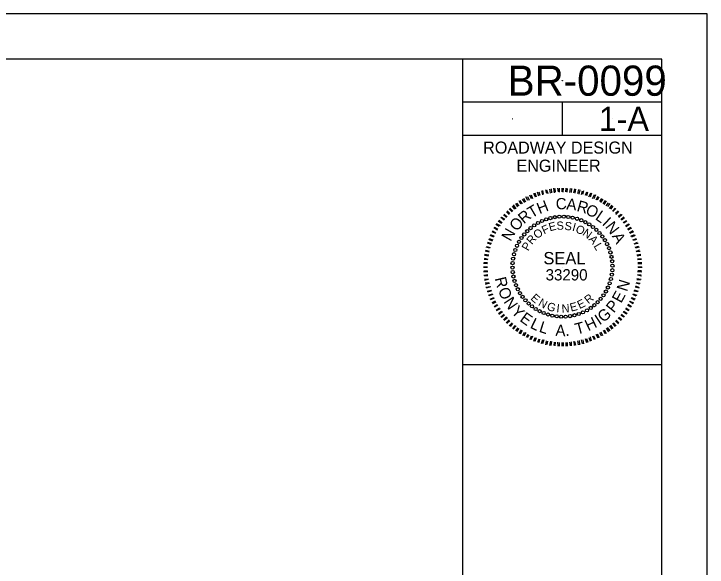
# Model space of a CAD drawing. Extents: x 1844369 to 1844800, y 671424 to 671721.
# Drawn here: x 1844552.92 to 1844581.79, y 671570.09 to 671593.11 of the extents above; entities that cross this region are included whole.
import ezdxf

# ---------------------------------------------------------------- set-up
doc = ezdxf.new("R2010")
doc.units = 0
for name, color, linetype in [('P_NCDOT_Roadway_Bridge', 7, 'Continuous'), ('Prop DSN Text', 7, 'Continuous'), ('Sheet PE Seal Cell', 7, 'Continuous'), ('Sheet Plan CELL', 7, 'Continuous'), ('Sheet_Clip_Boundary_CELL', 7, 'Continuous'), ('Sheet_Plan_CELL', 7, 'Continuous'), ('Sheet_Title_Block_Text', 7, 'Continuous')]:
    doc.layers.add(name, color=color, linetype=linetype)

msp = doc.modelspace()

# ---------------------------------------------------------------- linework, layer by layer
at = {"layer": 'P_NCDOT_Roadway_Bridge'}
for centre in [(1844575.761, 671590.327), (1844575.761, 671590.327), (1844573.689, 671588.741), (1844573.689, 671588.741), (1844577.833, 671588.741), (1844577.833, 671588.741), (1844571.617, 671588.051)]:
    msp.add_ellipse(centre, major_axis=(0, 0.00502), ratio=0.990582, dxfattribs=at)
at = {"layer": 'Sheet PE Seal Cell'}
for p, q in [((1844574.944, 671585.581), (1844574.902, 671585.739)), ((1844574.935, 671585.752), (1844574.966, 671585.599)), ((1844575.107, 671585.636), (1844575.076, 671585.788)), ((1844575.104, 671585.79), (1844575.147, 671585.632)), ((1844575.266, 671585.65), (1844575.24, 671585.814)), ((1844575.29, 671585.834), (1844575.3, 671585.663)), ((1844575.425, 671585.664), (1844575.409, 671585.852)), ((1844575.444, 671585.837), (1844575.464, 671585.689)), ((1844575.594, 671585.702), (1844575.575, 671585.849)), ((1844575.62, 671585.858), (1844575.629, 671585.687)), ((1844575.748, 671585.705), (1844575.746, 671585.859)), ((1844575.786, 671585.855), (1844575.783, 671585.689)), ((1844575.902, 671585.707), (1844575.923, 671585.851)), ((1844575.963, 671585.848), (1844575.949, 671585.687)), ((1844576.07, 671585.676), (1844576.101, 671585.844)), ((1844576.141, 671585.84), (1844576.127, 671585.68)), ((1844576.242, 671585.657), (1844576.273, 671585.824)), ((1844576.308, 671585.809), (1844576.282, 671585.654)), ((1844576.398, 671585.631), (1844576.445, 671585.805)), ((1844576.48, 671585.79), (1844576.444, 671585.611)), ((1844576.56, 671585.589), (1844576.602, 671585.751)), ((1844576.642, 671585.747), (1844576.6, 671585.585)), ((1844574.324, 671585.336), (1844574.241, 671585.497)), ((1844574.303, 671585.512), (1844574.374, 671585.356)), ((1844574.48, 671585.408), (1844574.409, 671585.564)), ((1844574.459, 671585.583), (1844574.518, 671585.432)), ((1844574.636, 671585.479), (1844574.576, 671585.63)), ((1844574.615, 671585.655), (1844574.669, 671585.492)), ((1844574.782, 671585.527), (1844574.727, 671585.689)), ((1844574.778, 671585.709), (1844574.825, 671585.563)), ((1844576.727, 671585.558), (1844576.776, 671585.703)), ((1844576.811, 671585.688), (1844576.762, 671585.543)), ((1844576.867, 671585.497), (1844576.938, 671585.661)), ((1844576.973, 671585.646), (1844576.914, 671585.477)), ((1844577.019, 671585.431), (1844577.102, 671585.59)), ((1844577.137, 671585.574), (1844577.066, 671585.411)), ((1844577.171, 671585.365), (1844577.254, 671585.524)), ((1844577.279, 671585.485), (1844577.206, 671585.35)), ((1844573.717, 671585.155), (1844573.817, 671585)), ((1844573.909, 671585.085), (1844573.816, 671585.223)), ((1844573.85, 671585.236), (1844573.953, 671585.122)), ((1844574.035, 671585.184), (1844573.959, 671585.328)), ((1844573.992, 671585.341), (1844574.086, 671585.203)), ((1844574.191, 671585.255), (1844574.103, 671585.404)), ((1844574.147, 671585.441), (1844574.23, 671585.28)), ((1844577.323, 671585.299), (1844577.408, 671585.429)), ((1844577.438, 671585.402), (1844577.348, 671585.26)), ((1844577.46, 671585.198), (1844577.55, 671585.34)), ((1844577.585, 671585.325), (1844577.49, 671585.171)), ((1844577.59, 671585.114), (1844577.686, 671585.239)), ((1844577.733, 671585.219), (1844577.637, 671585.093)), ((1844573.544, 671584.757), (1844573.43, 671584.877)), ((1844573.462, 671584.918), (1844573.576, 671584.799)), ((1844573.664, 671584.872), (1844573.549, 671584.992)), ((1844573.576, 671585.022), (1844573.691, 671584.902)), ((1844573.783, 671584.987), (1844573.685, 671585.113)), ((1844577.727, 671585.013), (1844577.828, 671585.149)), ((1844577.865, 671585.106), (1844577.757, 671584.986)), ((1844577.847, 671584.905), (1844577.955, 671585.025)), ((1844577.99, 671585.01), (1844577.866, 671584.883)), ((1844577.972, 671584.809), (1844578.087, 671584.912)), ((1844578.117, 671584.885), (1844577.992, 671584.759)), ((1844573.329, 671584.517), (1844573.197, 671584.63)), ((1844573.219, 671584.648), (1844573.361, 671584.559)), ((1844573.437, 671584.637), (1844573.305, 671584.75)), ((1844573.332, 671584.78), (1844573.464, 671584.667)), ((1844578.087, 671584.69), (1844578.208, 671584.776)), ((1844578.243, 671584.761), (1844578.107, 671584.639)), ((1844578.192, 671584.547), (1844578.323, 671584.657)), ((1844578.348, 671584.618), (1844578.222, 671584.52)), ((1844573.132, 671584.255), (1844572.99, 671584.345)), ((1844573.005, 671584.38), (1844573.164, 671584.297)), ((1844573.228, 671584.38), (1844573.091, 671584.482)), ((1844573.123, 671584.523), (1844573.255, 671584.41)), ((1844578.29, 671584.421), (1844578.428, 671584.514)), ((1844578.441, 671584.48), (1844578.32, 671584.394)), ((1844578.388, 671584.295), (1844578.521, 671584.376)), ((1844578.551, 671584.349), (1844578.408, 671584.245)), ((1844572.982, 671583.973), (1844572.83, 671584.039)), ((1844572.845, 671584.074), (1844572.992, 671583.997)), ((1844573.054, 671584.108), (1844572.912, 671584.198)), ((1844572.928, 671584.233), (1844573.07, 671584.143)), ((1844578.476, 671584.145), (1844578.609, 671584.227)), ((1844578.634, 671584.188), (1844578.49, 671584.112)), ((1844578.558, 671584.013), (1844578.702, 671584.089)), ((1844578.722, 671584.039), (1844578.566, 671583.968)), ((1844572.845, 671583.657), (1844572.693, 671583.723)), ((1844572.708, 671583.758), (1844572.865, 671583.704)), ((1844572.899, 671583.815), (1844572.747, 671583.88)), ((1844572.767, 671583.927), (1844572.919, 671583.861)), ((1844578.617, 671583.862), (1844578.768, 671583.921)), ((1844578.793, 671583.883), (1844578.637, 671583.812)), ((1844578.689, 671583.706), (1844578.84, 671583.765)), ((1844578.848, 671583.72), (1844578.702, 671583.672)), ((1844572.594, 671583.433), (1844572.756, 671583.39)), ((1844572.796, 671583.512), (1844572.638, 671583.566)), ((1844572.642, 671583.606), (1844572.804, 671583.564)), ((1844578.743, 671583.543), (1844578.882, 671583.608)), ((1844578.914, 671583.553), (1844578.762, 671583.521)), ((1844578.791, 671583.397), (1844578.949, 671583.44)), ((1844572.715, 671583.199), (1844572.548, 671583.23)), ((1844572.552, 671583.27), (1844572.714, 671583.228)), ((1844572.741, 671583.355), (1844572.579, 671583.397)), ((1844578.957, 671583.395), (1844578.804, 671583.364)), ((1844578.829, 671583.228), (1844578.991, 671583.283)), ((1844578.995, 671583.226), (1844578.847, 671583.206)), ((1844572.659, 671582.877), (1844572.498, 671582.891)), ((1844572.507, 671582.942), (1844572.657, 671582.905)), ((1844572.685, 671583.032), (1844572.512, 671583.051)), ((1844572.521, 671583.103), (1844572.693, 671583.084)), ((1844578.86, 671583.076), (1844579.029, 671583.113)), ((1844579.032, 671583.057), (1844578.868, 671583.03)), ((1844579.053, 671582.881), (1844578.882, 671582.871)), ((1844578.886, 671582.912), (1844579.045, 671582.926)), ((1844572.475, 671582.581), (1844572.641, 671582.579)), ((1844572.639, 671582.704), (1844572.479, 671582.718)), ((1844572.482, 671582.758), (1844572.648, 671582.756)), ((1844575.776, 671582.566), (1844575.776, 671582.566)), ((1844579.062, 671582.71), (1844578.897, 671582.712)), ((1844578.898, 671582.587), (1844579.064, 671582.584)), ((1844578.905, 671582.764), (1844579.071, 671582.762)), ((1844572.642, 671582.55), (1844572.476, 671582.553)), ((1844572.651, 671582.379), (1844572.481, 671582.37)), ((1844572.484, 671582.41), (1844572.643, 671582.425)), ((1844579.064, 671582.362), (1844578.892, 671582.381)), ((1844578.9, 671582.433), (1844579.049, 671582.424)), ((1844579.077, 671582.551), (1844578.911, 671582.553)), ((1844572.493, 671582.24), (1844572.658, 671582.266)), ((1844572.661, 671582.209), (1844572.507, 671582.206)), ((1844572.514, 671582.064), (1844572.679, 671582.09)), ((1844572.68, 671582.061), (1844572.523, 671582.018)), ((1844579.019, 671582.034), (1844578.859, 671582.048)), ((1844578.867, 671582.1), (1844579.034, 671582.069)), ((1844578.881, 671582.26), (1844579.042, 671582.246)), ((1844579.05, 671582.201), (1844578.883, 671582.232)), ((1844572.545, 671581.911), (1844572.693, 671581.931)), ((1844572.723, 671581.904), (1844572.549, 671581.854)), ((1844572.578, 671581.73), (1844572.747, 671581.768)), ((1844572.766, 671581.746), (1844572.591, 671581.697)), ((1844578.952, 671581.688), (1844578.79, 671581.73)), ((1844578.804, 671581.794), (1844578.956, 671581.728)), ((1844578.983, 671581.855), (1844578.826, 671581.909)), ((1844578.836, 671581.933), (1844579.003, 671581.902)), ((1844572.633, 671581.568), (1844572.79, 671581.61)), ((1844572.808, 671581.589), (1844572.646, 671581.534)), ((1844572.687, 671581.405), (1844572.85, 671581.459)), ((1844572.863, 671581.426), (1844572.7, 671581.371)), ((1844578.839, 671581.362), (1844578.687, 671581.428)), ((1844578.702, 671581.463), (1844578.854, 671581.397)), ((1844578.903, 671581.542), (1844578.736, 671581.573)), ((1844578.756, 671581.62), (1844578.913, 671581.566)), ((1844572.753, 671581.237), (1844572.909, 671581.309)), ((1844572.923, 671581.275), (1844572.767, 671581.204)), ((1844572.83, 671581.093), (1844572.974, 671581.169)), ((1844572.994, 671581.119), (1844572.849, 671581.043)), ((1844578.702, 671581.046), (1844578.56, 671581.135)), ((1844578.57, 671581.159), (1844578.717, 671581.081)), ((1844578.768, 671581.198), (1844578.621, 671581.276)), ((1844578.636, 671581.311), (1844578.788, 671581.245)), ((1844572.913, 671580.932), (1844573.045, 671581.013)), ((1844573.075, 671580.986), (1844572.926, 671580.898)), ((1844573.001, 671580.783), (1844573.138, 671580.876)), ((1844573.163, 671580.837), (1844573.002, 671580.754)), ((1844578.518, 671580.751), (1844578.388, 671580.835)), ((1844578.408, 671580.882), (1844578.545, 671580.781)), ((1844578.612, 671580.904), (1844578.465, 671580.982)), ((1844578.497, 671581.023), (1844578.639, 671580.934)), ((1844573.094, 671580.645), (1844573.231, 671580.738)), ((1844573.261, 671580.711), (1844573.119, 671580.606)), ((1844573.199, 671580.502), (1844573.33, 671580.612)), ((1844573.355, 671580.573), (1844573.229, 671580.475)), ((1844578.321, 671580.489), (1844578.191, 671580.573)), ((1844578.223, 671580.615), (1844578.343, 671580.507)), ((1844578.428, 671580.609), (1844578.292, 671580.71)), ((1844578.319, 671580.74), (1844578.455, 671580.639)), ((1844573.308, 671580.371), (1844573.433, 671580.498)), ((1844573.469, 671580.454), (1844573.338, 671580.344)), ((1844573.423, 671580.252), (1844573.548, 671580.378)), ((1844573.573, 671580.34), (1844573.453, 671580.225)), ((1844573.55, 671580.127), (1844573.663, 671580.259)), ((1844577.883, 671580.248), (1844577.998, 671580.129)), ((1844578.09, 671580.213), (1844577.975, 671580.333)), ((1844578.002, 671580.363), (1844578.105, 671580.249)), ((1844578.203, 671580.345), (1844578.088, 671580.465)), ((1844578.11, 671580.483), (1844578.235, 671580.387)), ((1844573.688, 671580.22), (1844573.58, 671580.1)), ((1844573.682, 671580.014), (1844573.794, 671580.146)), ((1844573.83, 671580.131), (1844573.712, 671579.987)), ((1844573.824, 671579.925), (1844573.915, 671580.038)), ((1844573.95, 671580.023), (1844573.854, 671579.898)), ((1844573.955, 671579.812), (1844574.061, 671579.961)), ((1844577.493, 671579.958), (1844577.581, 671579.809)), ((1844577.697, 671579.884), (1844577.592, 671580.027)), ((1844577.631, 671580.052), (1844577.729, 671579.926)), ((1844577.828, 671579.994), (1844577.735, 671580.131)), ((1844577.757, 671580.15), (1844577.867, 671580.019)), ((1844577.959, 671580.104), (1844577.844, 671580.223)), ((1844574.08, 671579.939), (1844573.997, 671579.78)), ((1844574.114, 671579.73), (1844574.187, 671579.865)), ((1844574.233, 671579.844), (1844574.149, 671579.714)), ((1844574.261, 671579.652), (1844574.334, 671579.787)), ((1844574.364, 671579.76), (1844574.296, 671579.637)), ((1844574.414, 671579.557), (1844574.48, 671579.709)), ((1844574.516, 671579.694), (1844574.45, 671579.542)), ((1844577.093, 671579.548), (1844577.033, 671579.699)), ((1844577.055, 671579.718), (1844577.131, 671579.573)), ((1844577.249, 671579.62), (1844577.172, 671579.764)), ((1844577.211, 671579.789), (1844577.287, 671579.645)), ((1844577.393, 671579.696), (1844577.317, 671579.84)), ((1844577.36, 671579.877), (1844577.432, 671579.721)), ((1844577.548, 671579.796), (1844577.466, 671579.928)), ((1844574.567, 671579.491), (1844574.633, 671579.643)), ((1844574.668, 671579.628), (1844574.613, 671579.471)), ((1844574.74, 671579.444), (1844574.79, 671579.589)), ((1844574.813, 671579.579), (1844574.775, 671579.429)), ((1844574.897, 671579.389), (1844574.945, 671579.563)), ((1844574.992, 671579.543), (1844574.933, 671579.374)), ((1844575.071, 671579.342), (1844575.102, 671579.509)), ((1844575.137, 671579.494), (1844575.117, 671579.35)), ((1844575.239, 671579.311), (1844575.275, 671579.49)), ((1844575.31, 671579.475), (1844575.279, 671579.307)), ((1844575.416, 671579.303), (1844575.425, 671579.452)), ((1844575.465, 671579.449), (1844575.439, 671579.293)), ((1844575.588, 671579.284), (1844575.574, 671579.443)), ((1844575.626, 671579.435), (1844575.629, 671579.281)), ((1844575.754, 671579.282), (1844575.751, 671579.436)), ((1844575.792, 671579.432), (1844575.794, 671579.278)), ((1844575.92, 671579.279), (1844575.917, 671579.433)), ((1844575.962, 671579.441), (1844575.96, 671579.276)), ((1844576.091, 671579.289), (1844576.076, 671579.448)), ((1844576.127, 671579.468), (1844576.119, 671579.29)), ((1844576.266, 671579.31), (1844576.245, 671579.485)), ((1844576.269, 671579.475), (1844576.312, 671579.318)), ((1844576.431, 671579.336), (1844576.405, 671579.5)), ((1844576.455, 671579.52), (1844576.476, 671579.344)), ((1844576.6, 671579.373), (1844576.562, 671579.543)), ((1844576.607, 671579.551), (1844576.645, 671579.381)), ((1844576.774, 671579.423), (1844576.72, 671579.585)), ((1844576.77, 671579.605), (1844576.813, 671579.448)), ((1844576.937, 671579.477), (1844576.877, 671579.628)), ((1844576.921, 671579.665), (1844576.964, 671579.507))]:
    msp.add_line(p, q, dxfattribs=at)
for centre in [(1844575.083, 671584.558), (1844575.262, 671584.611), (1844575.445, 671584.648), (1844575.631, 671584.668), (1844575.817, 671584.671), (1844576.004, 671584.658), (1844576.188, 671584.628), (1844576.369, 671584.582), (1844576.545, 671584.52), (1844574.584, 671584.306), (1844574.742, 671584.404), (1844574.909, 671584.489), (1844576.715, 671584.442), (1844576.877, 671584.349), (1844577.03, 671584.242), (1844574.296, 671584.067), (1844574.435, 671584.193), (1844577.173, 671584.122), (1844577.305, 671583.989), (1844574.056, 671583.782), (1844574.17, 671583.93), (1844577.424, 671583.845), (1844577.53, 671583.691), (1844573.871, 671583.458), (1844573.956, 671583.624), (1844577.622, 671583.529), (1844577.699, 671583.358), (1844573.746, 671583.106), (1844573.8, 671583.284), (1844577.76, 671583.182), (1844573.708, 671582.923), (1844577.805, 671583), (1844577.833, 671582.816), (1844573.681, 671582.55), (1844573.686, 671582.737), (1844577.845, 671582.629), (1844573.693, 671582.364), (1844577.819, 671582.257), (1844577.84, 671582.442), (1844573.722, 671582.179), (1844573.767, 671581.998), (1844577.781, 671582.074), (1844573.828, 671581.821), (1844573.905, 671581.651), (1844577.656, 671581.722), (1844577.726, 671581.895), (1844573.996, 671581.488), (1844577.471, 671581.398), (1844577.571, 671581.556), (1844574.102, 671581.334), (1844574.222, 671581.19), (1844574.353, 671581.058), (1844577.231, 671581.112), (1844577.357, 671581.25), (1844574.496, 671580.938), (1844574.649, 671580.831), (1844576.785, 671580.775), (1844576.943, 671580.874), (1844577.092, 671580.987), (1844574.812, 671580.738), (1844574.981, 671580.66), (1844575.158, 671580.598), (1844575.339, 671580.551), (1844575.523, 671580.521), (1844575.709, 671580.508), (1844575.896, 671580.512), (1844576.082, 671580.532), (1844576.265, 671580.569), (1844576.444, 671580.622), (1844576.618, 671580.691)]:
    msp.add_circle(centre, 0.0664, dxfattribs=at)
at = {"layer": 'Sheet Plan CELL'}
msp.add_line((1844579.905, 671578.512), (1844571.617, 671578.512), dxfattribs=at)
at = {"layer": 'Sheet_Clip_Boundary_CELL'}
msp.add_lwpolyline([(1844581.788, 671593.106), (1844440.123, 671593.106), (1844440.123, 671501.068), (1844581.788, 671501.068)], close=True, dxfattribs=at)
at = {"layer": 'Sheet_Plan_CELL'}
for p, q in [((1844579.905, 671591.223), (1844443.146, 671591.223)), ((1844571.615, 671502.951), (1844571.617, 671591.223)), ((1844579.903, 671502.951), (1844579.905, 671591.223)), ((1844579.905, 671589.431), (1844571.617, 671589.431)), ((1844575.761, 671588.051), (1844575.761, 671589.431)), ((1844579.905, 671588.051), (1844571.617, 671588.051))]:
    msp.add_line(p, q, dxfattribs=at)

# ---------------------------------------------------------------- texts
at = {"layer": 'Prop DSN Text'}
for s, height, p in [('ROADWAY DESIGN', 0.50203, (1844572.461, 671587.293)), ('ENGINEER', 0.502, (1844573.847, 671586.54))]:
    msp.add_text(s, height=height, dxfattribs=at).set_placement(p)
at = {"layer": 'Sheet PE Seal Cell'}
for s, height, rotation, p in [('C', 0.47, 4.1195, (1844575.503, 671584.959)), ('T', 0.47, 30.565, (1844574.481, 671584.596)), ('H', 0.47, 21.565, (1844574.806, 671584.77)), ('A', 0.47, 354.565, (1844575.911, 671584.97)), ('R', 0.47, 344.0819, (1844576.33, 671584.91)), ('O', 0.47, 335.0819, (1844576.686, 671584.796)), ('R', 0.47, 39.565, (1844574.155, 671584.348)), ('L', 0.47, 325.3965, (1844577.096, 671584.578)), ('O', 0.47, 49.8402, (1844573.863, 671584.031)), ('I', 0.47, 317.0132, (1844577.388, 671584.354)), ('F', 0.342, 25.3509, (1844574.996, 671583.928)), ('E', 0.342, 14.9192, (1844575.239, 671584.057)), ('S', 0.342, 4.0038, (1844575.527, 671584.117)), ('S', 0.342, 352.848, (1844575.834, 671584.127)), ('I', 0.342, 344.6348, (1844576.148, 671584.089)), ('O', 0.342, 335.4243, (1844576.275, 671584.04)), ('N', 0.47, 307.3965, (1844577.52, 671584.245)), ('N', 0.47, 60.423, (1844573.601, 671583.612)), ('O', 0.342, 37.1291, (1844574.707, 671583.726)), ('N', 0.342, 324.2692, (1844576.568, 671583.919)), ('R', 0.342, 49.0287, (1844574.486, 671583.487)), ('A', 0.342, 312.2371, (1844576.829, 671583.714)), ('A', 0.47, 298.3965, (1844577.812, 671583.862)), ('P', 0.342, 60.739, (1844574.34, 671583.22)), ('L', 0.342, 300.2563, (1844577.048, 671583.449)), ('SEAL', 0.5125, 0.0028, (1844574.969, 671582.687)), ('33290', 0.4698, 0.0028, (1844575.061, 671582.016)), ('R', 0.47, 283.2452, (1844572.942, 671582.105)), ('N', 0.47, 72.5046, (1844578.451, 671581.528)), ('O', 0.47, 293.5644, (1844573.067, 671581.613)), ('E', 0.342, 318.2926, (1844574.411, 671581.243)), ('R', 0.342, 38.711, (1844576.842, 671581.021)), ('E', 0.47, 61.4898, (1844578.208, 671581.043)), ('N', 0.47, 303.7838, (1844573.293, 671581.128)), ('N', 0.342, 330.7412, (1844574.727, 671580.99)), ('E', 0.342, 14.8978, (1844576.123, 671580.714)), ('E', 0.342, 26.1459, (1844576.479, 671580.82)), ('P', 0.47, 51.2741, (1844577.899, 671580.636)), ('Y', 0.47, 314.4613, (1844573.599, 671580.695)), ('G', 0.342, 343.6968, (1844575.088, 671580.796)), ('I', 0.342, 353.2466, (1844575.498, 671580.697)), ('N', 0.342, 3.1977, (1844575.736, 671580.675)), ('G', 0.47, 40.1342, (1844577.465, 671580.244)), ('E', 0.47, 324.1361, (1844573.954, 671580.349)), ('I', 0.47, 33.2125, (1844577.301, 671580.141)), ('L', 0.47, 333.9963, (1844574.383, 671580.059)), ('L', 0.47, 342.2461, (1844574.757, 671579.885)), ('T', 0.47, 15.1355, (1844576.356, 671579.756)), ('H', 0.47, 25.3568, (1844576.835, 671579.899)), ('A', 0.47, 357.5853, (1844575.464, 671579.713)), ('.', 0.47, 3.2238, (1844575.889, 671579.704))]:
    msp.add_text(s, height=height, rotation=rotation, dxfattribs=at).set_placement(p)
at = {"layer": 'Sheet_Title_Block_Text'}
for s, height, p in [('BR-0099', 1.2551, (1844573.483, 671589.7)), ('1-A', 1.0041, (1844577.275, 671588.239))]:
    msp.add_text(s, height=height, dxfattribs=at).set_placement(p)

doc.saveas('drawing.dxf')
